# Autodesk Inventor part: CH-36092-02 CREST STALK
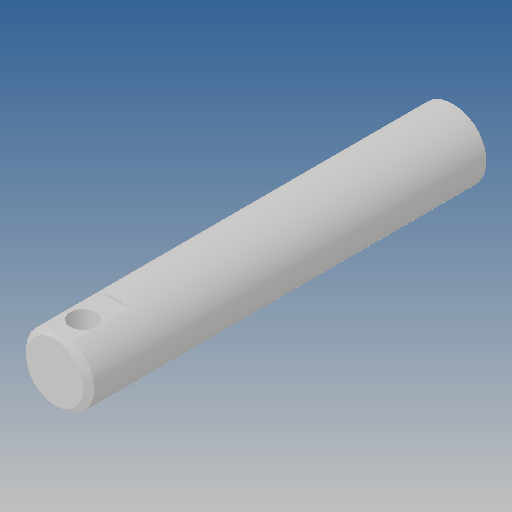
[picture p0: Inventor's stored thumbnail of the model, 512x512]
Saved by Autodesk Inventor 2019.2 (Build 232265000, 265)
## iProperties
Created: 2012-09
Part Number: CH-36092-02 CREST STALK
Material: Ogólny
Document SubType Name: Modeling
Designer: CADENGINEERING4
Density: 1 g/cm^3
Appearance: Domyślna
Author: CADENGINEERING4
Revision Number: ÈÎºÎ
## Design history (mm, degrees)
feature "¾µÏò3"
node "Bryła1"
